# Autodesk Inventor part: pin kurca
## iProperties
Created: 2006-04
Part Number: pin kurca
Document SubType Name: Modeling
Designer: Калинин
Author: Калинин
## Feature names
1. Выдавливание1 [Extrusion]
2. Вращение1 [Revolution]
3. Вращение2 [Revolution]
